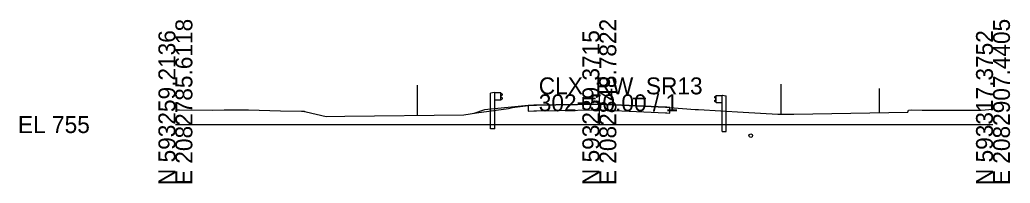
# Model space of a CAD drawing. Extents: x -26 to 2138, y -10 to 4518.
# Drawn here: x -25.7 to 137.8, y 2490.3 to 2517.3 of the extents above; entities that cross this region are included whole.
import ezdxf

# ---------------------------------------------------------------- set-up
doc = ezdxf.new("R2010")
doc.units = 0
for name, color, linetype in [('GK_Cells', 7, 'Continuous'), ('MD_X_Asphalt_Pavement', 7, 'Continuous'), ('RD_P_Cells', 7, 'Continuous'), ('RW_P_Esmt_SH', 7, 'Continuous'), ('RW_X_Esmt_SH', 7, 'Continuous'), ('UT_X_Water', 7, 'Continuous'), ('XS_P_Finished_Grade', 7, 'Continuous'), ('XS_X_Ground_Line', 7, 'Continuous')]:
    doc.layers.add(name, color=color, linetype=linetype)

msp = doc.modelspace()

# ---------------------------------------------------------------- linework, layer by layer
at = {"layer": 'GK_Cells'}
for p, q in [((70, 2500), (70, 2505)), ((0, 2500), (70, 2500)), ((70, 2500), (135, 2500))]:
    msp.add_line(p, q, dxfattribs=at)
at = {"layer": 'MD_X_Asphalt_Pavement'}
msp.add_lwpolyline([(59.19, 2503.21), (58.27, 2503.18), (58.27, 2502.22), (59.19, 2502.25), (59.61, 2502.28), (62.81, 2502.32), (70.05, 2502.44), (77.34, 2502.1), (80.95, 2501.95), (81.13, 2501.92), (81.66, 2501.88), (81.66, 2502.84), (81.13, 2502.88), (80.95, 2502.9), (77.34, 2503.05), (70.05, 2503.4), (62.81, 2503.27), (59.61, 2503.23), (59.19, 2503.21)], dxfattribs=at)
at = {"layer": 'RD_P_Cells'}
for p, q in [((52.1, 2505.21), (52.05, 2505.19)), ((52.05, 2499.29), (52.05, 2505.19)), ((52.64, 2505.29), (52.1, 2505.21)), ((52.72, 2505.25), (52.64, 2505.29)), ((53.72, 2505.25), (52.72, 2505.25)), ((52.72, 2499.29), (52.72, 2505.25)), ((53.72, 2504.06), (52.72, 2504.06)), ((53.72, 2504.06), (53.72, 2505.25)), ((53.81, 2505.15), (53.72, 2505.17)), ((53.72, 2504.14), (53.81, 2504.16)), ((53.73, 2504.66), (53.73, 2504.7)), ((53.73, 2504.61), (53.73, 2504.66)), ((53.76, 2504.77), (53.97, 2504.91)), ((53.97, 2504.4), (53.76, 2504.54)), ((53.97, 2505.04), (53.81, 2505.15)), ((53.81, 2504.16), (53.97, 2504.27)), ((89.03, 2504.61), (89.19, 2504.72)), ((89.24, 2504.33), (89.03, 2504.48)), ((89.03, 2503.97), (89.24, 2504.11)), ((89.19, 2503.73), (89.03, 2503.84)), ((89.19, 2504.72), (89.28, 2504.73)), ((89.28, 2503.71), (89.19, 2503.73)), ((89.27, 2504.22), (89.27, 2504.27)), ((89.27, 2504.18), (89.27, 2504.22)), ((89.28, 2503.63), (89.28, 2504.82)), ((89.28, 2504.82), (90.28, 2504.82)), ((90.28, 2504.82), (90.36, 2504.86)), ((90.28, 2498.86), (90.28, 2504.82)), ((90.36, 2504.86), (90.9, 2504.78)), ((90.9, 2504.78), (90.95, 2504.75)), ((90.95, 2498.86), (90.95, 2504.75)), ((89.28, 2503.63), (90.28, 2503.63)), ((52.72, 2499.29), (52.05, 2499.29)), ((90.28, 2498.86), (90.95, 2498.86))]:
    msp.add_line(p, q, dxfattribs=at)
for points in [[(53.74, 2504.72), (53.74, 2504.6), (53.73, 2504.6), (53.73, 2504.72)], [(53.74, 2504.68), (53.74, 2504.63), (53.76, 2504.63), (53.76, 2504.68)], [(89.26, 2504.25), (89.26, 2504.19), (89.24, 2504.19), (89.24, 2504.25)], [(89.26, 2504.28), (89.26, 2504.16), (89.27, 2504.16), (89.27, 2504.28)]]:
    msp.add_lwpolyline(points, close=True, dxfattribs=at)
for centre, start, end in [((53.81, 2504.7), 124.962, 180), ((53.81, 2504.61), 180, 235.038), ((53.92, 2504.97), 304.962, 54.7677), ((53.92, 2504.34), 304.962, 54.7677), ((89.08, 2504.54), 125.2323, 235.038), ((89.08, 2503.91), 125.2323, 235.038), ((89.19, 2504.27), 0, 55.038), ((89.19, 2504.18), 304.962, 0)]:
    msp.add_arc(centre, 0.0781, start, end, dxfattribs=at)
at = {"layer": 'RW_P_Esmt_SH'}
msp.add_line((116.27, 2501.95), (116.27, 2505.95), dxfattribs=at)
at = {"layer": 'RW_X_Esmt_SH'}
for p, q in [((40, 2501.52), (40, 2506.52)), ((100, 2501.71), (100, 2506.71))]:
    msp.add_line(p, q, dxfattribs=at)
at = {"layer": 'UT_X_Water'}
msp.add_circle((95, 2498.17), 0.3, dxfattribs=at)
at = {"layer": 'XS_P_Finished_Grade'}
for p, q in [((51.05, 2502.46), (49.28, 2501.86)), ((58.27, 2503.18), (51.05, 2502.46))]:
    msp.add_line(p, q, dxfattribs=at)
at = {"layer": 'XS_X_Ground_Line'}
msp.add_lwpolyline([(0, 2502.43), (0.69, 2502.42), (6.13, 2502.41), (8.04, 2502.46), (12.08, 2502.45), (17.33, 2502.29), (20.8, 2502.24), (21.32, 2502.2), (21.32, 2502.19), (21.61, 2502.13), (24.92, 2501.33), (27.97, 2501.37), (47.65, 2501.62), (49.7, 2501.93), (54.98, 2502.68), (55.68, 2502.81), (56.47, 2502.92), (58.27, 2503.18), (59.19, 2503.21), (59.61, 2503.23), (62.81, 2503.27), (70.05, 2503.4), (77.34, 2503.05), (80.95, 2502.9), (81.13, 2502.88), (81.66, 2502.84), (85.82, 2502.51), (86.12, 2502.49), (86.39, 2502.47), (93.76, 2502.04), (99.5, 2501.71), (101.27, 2501.72), (102.12, 2501.73), (120.96, 2502.03), (121.07, 2502.37), (121.56, 2502.45), (123.28, 2502.4), (133.03, 2502.39), (135, 2502.53)], dxfattribs=at)

# ---------------------------------------------------------------- texts
msp.add_text('-', height=0.0001).set_placement((0, 2500))
at = {"layer": 'GK_Cells'}
for s, p in [('E 2082785.6118', (2.8, 2490)), ('E 2082848.7822', (72.8, 2490)), ('E 2082907.4405', (137.8, 2490)), ('N 593259.2136', (0, 2490)), ('N 593289.3715', (70, 2490)), ('N 593317.3752', (135, 2490))]:
    msp.add_text(s, height=2.8, rotation=90, dxfattribs=at).set_placement(p)
for s, p in [('CLX_RW_SR13', (60, 2505)), ('302+50.00 / 1', (60, 2502.2)), ('EL 755', (-26, 2498.6))]:
    msp.add_text(s, height=2.8, dxfattribs=at).set_placement(p)

doc.saveas('drawing.dxf')
